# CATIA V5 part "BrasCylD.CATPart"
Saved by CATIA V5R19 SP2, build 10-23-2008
Part number: CylC.1
Bounding box of the stored display mesh (mm): x -45 to 45, y -44.99 to 44.99, z -15 to 405.981
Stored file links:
  C:\Users\Vianney\Documents\Garantie\Cours\2A\IAO\IAO-proj-Catia\BrasCylD.CATPart
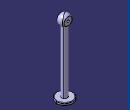
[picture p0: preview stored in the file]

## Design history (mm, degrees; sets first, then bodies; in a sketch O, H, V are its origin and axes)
Parameters
  LbrasD = 350 mm
  Dmc = 12 mm
  DbrasCylD = 30 mm
  EcorpcylD = 5 mm
  DCyldExt = 100 mm
Body1 (main body)
  Sketch1 on zx-plane, origin (0, 0, 0), H (-1, 0, 0), V (0, 0, 1)
    point P1 (0, 375.9808)
    line L1 (15, 0) -> (15, 350)
    arc A1 centre (0, 375.9808) radius 30 from (15, 350) to (0, 405.9808) ccw
    point P4 (15, 401.9615)
    point P5 (0, 405.9808)
    line L2 (0, 405.9808) -> (0, 0)
    line L3 (0, 0) -> (15, 0)
    distance L1 L2 = 15 {= DbrasCylD /2}
    length L1 = 350 {= LbrasD}
    radius A1 = 30
    coincidence: P1 V, A1 P4, P4 L1, P5 V
    vertical: L1 V, L2 V
    horizontal: L3 H
  Shaft1: profile Sketch1, axis Sketch1.L2, angle 360
  Sketch2 on zx-plane, origin (0, 0, 0), H (-1, 0, 0), V (0, 0, 1)
    circle A1 centre (0, 375.9808) radius 6
    point P1 (0, 375.9808)
    reference projected arc E1 centre (0, 375.9808) radius 30 from (22.5, 356.1376) to (0, 405.9808) ccw from Sketch1.A1
    radius A1 = 6 {= Dmc /2}
    coincidence: P1 V
    concentricity: A1 E1
  Pocket1: profile Sketch2, direction (0, -1, 0), through (limit type 6), opposite side length 44
  Sketch3 on yz-plane, origin (0, 0, 0), H (0, 1, 0), V (0, 0, 1)
    point P1 (-32, 353)
    line L1 (-32, 353) -> (-20, 353)
    line L2 (-20, 353) -> (-20, 401)
    line L3 (-20, 401) -> (-32, 401)
    line L4 (-32, 401) -> (-32, 353)
    point P2 (-20, 353)
    point P3 (-20, 401)
    point P4 (-32, 401)
    reference projected line E1 (-15, 350) -> (15, 350) from edge [face of Shaft1 from Sketch1.L1 | face of Shaft1 from Sketch1.A1]
    reference projected line E2 (0, 325) -> (0, 380.9808) from Sketch1.A1
    reference projected line E3 (0, 405.9808) -> (0, 0) from Sketch1.L2
    point P7 (32, 353)
    point P8 (20, 353)
    point P9 (20, 401)
    point P10 (32, 401)
    line L5 (32, 353) -> (20, 353)
    line L6 (20, 353) -> (20, 401)
    line L7 (20, 401) -> (32, 401)
    line L8 (32, 401) -> (32, 353)
    distance E1 L1 = 3
    distance L2 E2 = 20
    distance L4 L2 = 12
    distance L3 L1 = 48
    horizontal: L1 H, L3 H
    vertical: L2 V, L4 V
    symmetry: P1 P7 E3, P2 P8 E3, P3 P9 E3, P4 P10 E3, L1 L5 E3, L2 L6 E3, L3 L7 E3, L4 L8 E3
  Pocket2: profile Sketch3, direction (1, 0, 0), length 30, opposite side length 44
  Sketch4 on xy-plane, origin (0, 0, 0), H (1, 0, 0), V (0, 1, 0)
    circle A1 centre (0, 0) radius 45
    radius A1 = 45 {= DCyldExt /2-EcorpcylD}
  Pad1: profile Sketch4, direction (0, 0, -1), length 15
  Fillet1: radius 3, on edge [end face of Pad1 | face of Pad1 from Sketch4.A1]; edge [face of Pad1 from Sketch4.A1 | start face of Pad1]
  Fillet2: radius 15, on edge [face of Shaft1 from Sketch1.L1 | face of Shaft1 from Sketch1.A1]
Current feature: Fillet1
